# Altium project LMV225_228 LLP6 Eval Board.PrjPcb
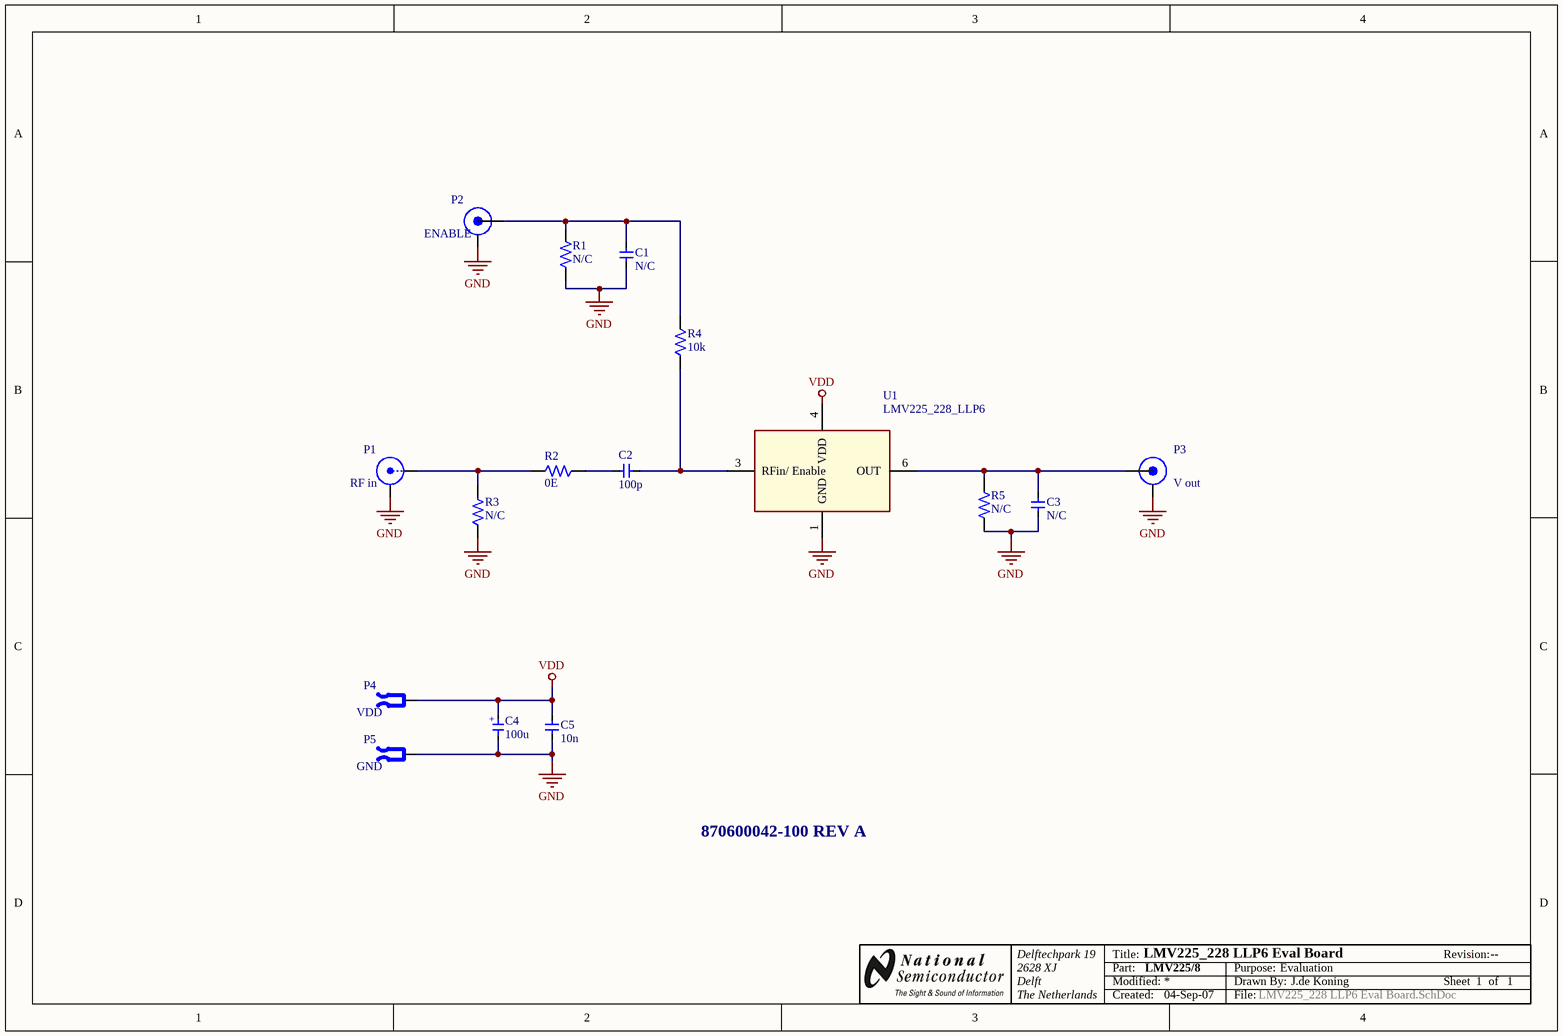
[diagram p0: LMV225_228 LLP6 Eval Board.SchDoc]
1 sheet, 17 parts. Net scope: global (net labels, ports and power ports of the same name join across sheets).
Board file: LMV225_228 LLP6 Eval Board.PcbDoc

## Sheet LMV225_228 LLP6 Eval Board.SchDoc
size A4; Address1: Delftechpark 19; Address2: 2628 XJ; Address3: Delft; Address4: The Netherlands; PageSetup: Record=PageOptions|CenterHorizontal=True|CenterVertical=True|PrintScale=0.97|XCorrection=1.00|YCorrection=1.00|PrintKind=0|BorderSize=5000000|LeftOffset=0|BottomOffset=0|Orientation=2|PaperLength=1000|PaperWidth=1000|Scale=100|PaperSource=7|PrintQuality=-4|MediaType=1|DitherType=10|PaperKind=A4|PrintScaleMode=1

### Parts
*  =Part: LMV225/8  =Created: 04-Sep-07  =Purpose: Evaluation  =DrawnBy: J.de Koning  =SheetNumber: 1  =Title: LMV225_228 LLP6 Eval Board  (hidden comment: Title Block National 2)  (graphical)
C1  N/C  [SM/RC_0603]
C2  100p  [SM/RC_0603]
C3  N/C  [SM/RC_0603]
C4  100u  [CASE C]
C5  10n  [SM/RC_0603]
P1  RF in  [SMA-SIDE]
P2  ENABLE  [BNC_RA]
P3  V out  [BNC_RA]
P4  VDD  [Banana_COLOR]
P5  GND  [Banana_COLOR]
R1  N/C  [SM/RC_0603]
R2  0E  [SM/RC_0603]
R3  N/C  [SM/RC_0603]
R4  10k  [SM/RC_0603]
R5  N/C  [SM/RC_0603]
U1  LMV225_228_LLP6  [SDB06A]

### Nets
GND: C1.1 C3.1 C4.2 C5.1 P1.2(Y) P2.2(GND) P3.2(GND) P5.1 R1.1 R3.2 R5.2 U1.1(GND)
VDD: C4.1 C5.2 P4.1 U1.4(VDD)
NetC1_2: C1.2 P2.1(Center) R1.2 R4.2
NetC2_1: C2.1 R4.1 U1.3(RFin/_Enable)
NetC2_2: C2.2 R2.1
NetC3_2: C3.2 P3.1(Center) R5.1 U1.6(OUT)
NetP1_1: P1.1(X) R2.2 R3.1

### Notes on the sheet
- 870600042-100 REV A

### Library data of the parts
C1-C3 C5 = C smd: TOLERANCE: 10%; PSpiceTemplate: C^@REFDES %1 %2 ?TOLERANCE|C^@REFDES| @VALUE ?IC/IC=@IC/ ?TOLERANCE|\n.model C^@REFDES CAP C=1 DEV=@TOLERANCE%|; voltage: 16V
C4 = C tantaal: voltage: *V
P1 = SMA: SMA Connector; Rule: UNIONINDEX{}0[]RULEKIND{}PolygonConnect[]NETSCOPE{}DifferentNets[]LAYERKIND{}SameLayer[]NAME{}Schematic Polygon Connect Style[]CONNECTSTYLE{}Relief[]RELIEFCONDUCTORWIDTH{}27.5591mil[]RELIEFENTRIES{}4[]POLYGONRELIEFANGLE{}90 Angle[]UNIT{}Imperial[]PcbType{}ProtelPcb; Rule: UNIONINDEX{}0[]RULEKIND{}PlaneConnect[]NETSCOPE{}DifferentNets[]LAYERKIND{}SameLayer[]NAME{}Schematic Power Plane Connect Style[]PLANECONNECTSTYLE{}Relief[]RELIEFEXPANSION{}27.5591mil[]RELIEFENTRIES{}4[]RELIEFCONDUCTORWIDTH{}19.685mil[]RELIEFAIRGAP{}19.685mil[]UNIT{}Imperial[]PcbType{}ProtelPcb
P2 P3 = BNC: Rule: UNIONINDEX{}0[]RULEKIND{}PolygonConnect[]NETSCOPE{}DifferentNets[]LAYERKIND{}SameLayer[]NAME{}Schematic Polygon Connect Style[]CONNECTSTYLE{}Relief[]RELIEFCONDUCTORWIDTH{}27.5591mil[]RELIEFENTRIES{}4[]POLYGONRELIEFANGLE{}90 Angle[]UNIT{}Imperial[]PcbType{}ProtelPcb; Rule: UNIONINDEX{}0[]RULEKIND{}PlaneConnect[]NETSCOPE{}DifferentNets[]LAYERKIND{}SameLayer[]NAME{}Schematic Power Plane Connect Style[]PLANECONNECTSTYLE{}Relief[]RELIEFEXPANSION{}27.5591mil[]RELIEFENTRIES{}4[]RELIEFCONDUCTORWIDTH{}19.685mil[]RELIEFAIRGAP{}19.685mil[]UNIT{}Imperial[]PcbType{}ProtelPcb
P4 P5 = Banana socket: Rule: UNIONINDEX{}0[]RULEKIND{}PlaneConnect[]NETSCOPE{}DifferentNets[]LAYERKIND{}SameLayer[]NAME{}Schematic Power Plane Connect Style[]PLANECONNECTSTYLE{}Relief[]RELIEFEXPANSION{}30mil[]RELIEFENTRIES{}4[]RELIEFCONDUCTORWIDTH{}19.685mil[]RELIEFAIRGAP{}19.685mil[]UNIT{}Imperial[]PcbType{}ProtelPcb; Rule: UNIONINDEX{}0[]RULEKIND{}PolygonConnect[]NETSCOPE{}DifferentNets[]LAYERKIND{}SameLayer[]NAME{}Schematic Polygon Connect Style[]CONNECTSTYLE{}Relief[]RELIEFCONDUCTORWIDTH{}29.528mil[]RELIEFENTRIES{}4[]POLYGONRELIEFANGLE{}90 Angle[]UNIT{}Imperial[]PcbType{}ProtelPcb
R1-R5 = R smd: TOLERANCE: 1%; PSpiceTemplate: R^@REFDES %1 %2 ?TOLERANCE|R^@REFDES| @VALUE  ?TOLERANCE|\n.model R^@REFDES RES R=1 DEV=@TOLERANCE%|
U1 = LMV225_226_228_1: LLP6; PSpiceTemplate: C^@REFDES %1 %2 ?TOLERANCE|C^@REFDES| @VALUE ?IC/IC=@IC/ ?TOLERANCE|\n.model C^@REFDES CAP C=1 DEV=@TOLERANCE%|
